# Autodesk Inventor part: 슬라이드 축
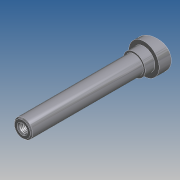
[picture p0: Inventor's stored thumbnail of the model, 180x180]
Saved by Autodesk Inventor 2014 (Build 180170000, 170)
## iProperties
Created: 2012-05
Part Number: 슬라이드 축
Document SubType Name: 모델링
Designer: SeoGD™
Mass: 19.8501 g
Surface Area: 63.0734 cm^2
Volume: 19.8501 cm^3
Density: 1 g/cm^3
Material: 강철, 연강
Appearance: 강철
변환 표준: STEP AP214IS
파일 이름: C:\Users\SeoGD\Desktop\?쒗뿕\異?stp
전처리기: Build: 253, Release: 2010 SP1 - Date: Wed 07/29/2009
전송 단위: 밀리미터
불확실성: 0.01
Author: SeoGD™
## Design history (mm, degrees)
sketch "스케치1"
  geometry: L1 (0, 100)-(7.5, 100); L2 (7.5, 100)-(7.5, 0); L3 (7.5, 0)-(12.5, 0); L4 (12.5, 0)-(12.5, -17); L5 (12.5, -17)-(0, -17); L6 (0, -17)-(0, 100); 1 further point
  constraints: 12 end point, 2 parallel, 2 point on line, 1 perpendicular, 1 vertical
  dimensions: "d0" = 100 distance from line of L1 point (0, 0); "d1" = 15 diameter of L2 L6; "d2" = 25 diameter of L4 L6; "d3" = 17 distance of L3.end L4.end
revolve "회전1" sketch "스케치1" stored, may be unused: angle "d4" = 90 deg
sketch "스케치2"
  geometry: L1 (12.5, 0)-(12.5, -17) reference; L2 (-12.5, -17)-(12.5, -17) reference; L3 (-12.5, 0)-(-12.5, -17) reference; L4 (12.5, -5)-(-12.5, -11.699); L5 (-12.5, 0)-(12.5, 0) reference; 1 further point
  constraints: 2 end point, 2 point on line
  dimensions: "d5" = 75 deg angle of L1 L4; "d6" = 5 distance from line of L4.start L5
extrude "돌출1" cut sketch "스케치2" stored distance "d7" = 10; taper "d8" = 0 deg
chamfer "모따기1" distance "d9" = 1; stored, may be unused: second distance "d10" = 2, angle "d11" = 45 deg
fillet "모깎기1" dims "d12" = 0.5
hole "구멍1" diameter "d15" = 6.647; stored, may be unused: countersink angle "d19" = 90 deg, drill point angle "d21" = 118 deg; dims "d13" = 10, "d14" = 10, "d16" = 17, "d17" = 4, "d18" = 2, "d20" = 20
chamfer "모따기2" distance "d22" = 1; stored, may be unused: second distance "d23" = 2, angle "d24" = 45 deg
sketch "스케치3"
  geometry: C1 r 9 at (0, 0); 1 further point
  constraints: 1 centre point, 1 coincident
  dimensions: "d25" = 18 diameter of C1
extrude "돌출2" join sketch "스케치3" distance "d26" = 8; taper "d27" = 0 deg
node "솔리드1"
node "솔리드 본체"
node "곡면 본체"
node "솔리드2"
